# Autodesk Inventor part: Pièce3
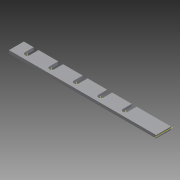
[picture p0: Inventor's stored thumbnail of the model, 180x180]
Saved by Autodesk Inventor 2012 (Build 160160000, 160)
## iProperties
Created: 2016-01
Part Number: Pièce3
Material: Default
Document SubType Name: Modeling
Designer: wmfoihay
Density: 1 g/cm^3
Author: wmfoihay
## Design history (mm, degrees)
sketch "Esquisse1"
  geometry: L1 (0, 0)-(600, 0); L2 (600, 0)-(600, 65); L3 (600, 65)-(0, 65); L4 (0, 65)-(0, 0)
  constraints: 8 end point, 1 horizontal, 1 parallel, 1 perpendicular
  dimensions: "d0" = 600 distance of L1.start L1.end (= Plat_long2); "d1" = 65 distance of L1.end L2.end (= Plat_larg); "d2" = 600 distance of L2.end L3.end (= Plat_long)
extrude "Extrusion1" new body sketch "Esquisse1" distance "d3" = 12 (= plat_ep); taper "d4" = 0 deg
sketch "Esquisse2"
  geometry: L1 (0, 0)-(-600, 0) reference; L2 (-600, 65)-(0, 65) reference; L3 (-600, 0)-(-600, 65) reference; L4 (-600, 0)-(0, 0); L5 (-703.035, 15)-(114.337, 15); L6 (-60, 25)-(-60, 65); L7 (-40, 25)-(-40, 65); L8 (0, 65)-(0, 0) reference; L9 (-60, 65)-(-40, 65); A1 r 10 centre (-50, 25) between (-60, 25) and (-40, 25); 2 further points
  constraints: 10 end point, 3 perpendicular, 3 tangent, 2 point on circle, 2 point on line, 1 centre point, 1 parallel
  dimensions: "d5" = 15 distance between parallel lines of L1 L5; "d9" = 20 diameter of A1; "d29" = 50 distance from line of L8 A1.centre; "d31" = 0 distance between parallel lines of L2 L9
extrude "Extrusion4" cut sketch "Esquisse2" stored distance "d24" = 10; taper "d25" = 0 deg
pattern_linear "Réseau rectangulaire1" dims "d28" = 100 (= Plat_entrax)
sketch "Esquisse3"
  geometry: L1 (0, 65)-(12, 65) reference; L2 (0, 0)-(12, 0) reference; L3 (6, 65)-(6, 90.15); C1 r 30.15 at (6, 90.15)
  constraints: 2 end point, 1 centre point, 1 coincident, 1 midpoint, 1 perpendicular
  dimensions: "d32" = 60.3 diameter of C1; "d33" = 60 distance edge to line of C1 L2
extrude "Extrusion5" cut sketch "Esquisse3" stored distance "d34" = 0; taper "d35" = 0 deg
node "Axe de construction1"
node "Solide1"
other parameters: "plat_ep" = 12 [user parameter; used in 1 equation term], "Plat_long" = 600 [user parameter; used in 1 equation term], "Plat_larg" = 65 [user parameter; used in 1 equation term], "Plat_long2" = 600 [user parameter; used in 1 equation term], "Plat_entrax" = 100 [user parameter; used in 1 equation term]
